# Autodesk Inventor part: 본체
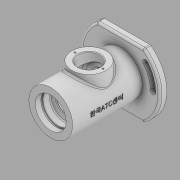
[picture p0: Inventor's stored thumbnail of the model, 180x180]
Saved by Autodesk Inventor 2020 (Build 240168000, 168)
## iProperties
Created: 2022-05
Part Number: 본체
Material: 일반
Document SubType Name: Modeling
Designer: Student
Mass: 254.633 g
Surface Area: 622.213 cm^2
Volume: 254.633 cm^3
Density: 1 g/cm^3
Appearance: 기본값
Author: Student
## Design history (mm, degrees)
sketch "스케치1"
  geometry: L1 (47, 92.583)-(47, -88.297); L2 (69.5, 10.285)-(69.5, 2.285); L3 (69.5, 2.285)-(71, 2.285); L4 (71, 2.285)-(71, -0.715); L5 (71, -0.715)-(69.5, -0.715); L6 (69.5, -0.715)-(69.5, -11.715); L7 (69.5, -11.715)-(65.5, -11.715); L8 (64.5, -12.715)-(64.5, -13.965); L9 (64.5, -13.965)-(65.5, -13.965); L10 (65.5, -13.965)-(65.5, -15.715); L11 (65.5, -15.715)-(64.5, -15.715); L12 (64.5, -15.715)-(64.5, -25.715); L13 (65.5, -26.715)-(71, -26.715); L14 (74, -29.715)-(74, -61.715); L15 (71, -64.715)-(65.5, -64.715); L16 (64.5, -65.715)-(64.5, -75.115); L17 (63.9, -75.715)-(62, -75.715); L18 (62, -75.715)-(62, -77.715); L19 (59, -80.715)-(58, -80.715); L20 (58, -80.715)-(58, -82.715); L21 (58, -82.715)-(61.5, -82.715); L22 (62, -83.215)-(62, -89.715); L23 (62.577, -90.715)-(65.456, -90.715); L24 (67.897, -91.971)-(77, -104.715); L25 (69.5, 10.285)-(79, 10.285); L26 (79, 10.285)-(79, -91.715); L27 (79, -91.715)-(105, -91.715); L28 (105, -91.715)-(105, -101.715); L29 (105, -101.715)-(83, -101.715); L30 (83, -101.715)-(83, -104.715); L31 (83, -104.715)-(77, -104.715); L32 (65.5, -11.715)-(64.5, -12.715); L33 (64.5, -25.715)-(65.5, -26.715); L34 (65.5, -64.715)-(64.5, -65.715); L35 (62, -89.715)-(62.577, -90.715); A1 r 3 centre (71, -29.715) between (74, -29.715) and (71, -26.715); A2 r 3 centre (71, -61.715) between (71, -64.715) and (74, -61.715); A3 r 0.6 centre (63.9, -75.115) between (63.9, -75.715) and (64.5, -75.115); A4 r 3 centre (59, -77.715) between (59, -80.715) and (62, -77.715); A5 r 0.5 centre (61.5, -83.215) between (62, -83.215) and (61.5, -82.715); A6 r 3 centre (65.456, -93.715) between (67.897, -91.971) and (65.456, -90.715); 11 further points
  constraints: 70 end point, 24 point on line, 23 perpendicular, 12 point on circle, 12 tangent, 6 centre point, 2 horizontal, 2 vertical, 1 equal radius
  dimensions: "d0" = 47 distance from line of point (0, 0) L1; "d3" = 22 diameter of L20 L1; "d4" = 48 diameter of L4 L1; "d6" = 45 diameter of L6 L1; "d7" = 45 diameter of L2 L1; "d8" = 35 diameter of L8 L1; "d10" = 54 diameter of L14 L1; "d11" = 30 diameter of L18 L1; "d12" = 40 diameter of point (67, -90.715) L1; "d13" = 30 diameter of L22 L1; "d14" = 60 diameter of L24.end L1; "d15" = 72 diameter of L30.end L1; "d16" = 64 diameter of L26 L1; "d17" = 8 distance of L2.start L2.end; "d18" = 3 distance of L3.end L4.end; "d20" = 37 diameter of L10 L1; "d21" = 1.75 distance of L9.end L10.end; "d22" = 4 vertical distance of L10.end point (64.5, -11.715); "d23" = 11 distance of L11.end point (64.5, -26.715); "d24" = 38 distance of point (74, -26.715) point (74, -64.715); "d25" = 11 distance of point (64.5, -64.715) point (64.5, -75.715); "d26" = 5 distance of L17.end point (62, -80.715); "d27" = 14 vertical distance of L24.end point (67, -90.715); "d28" = 115 distance from line of L24.end L25; "d29" = 3 distance of L29.end L30.end; "d30" = 13 distance from line of L30.end L27; "d31" = 116 diameter of L28 L1; "d32" = 8 distance of point (62, -90.715) point (62, -82.715); "d54" = 101.71474 distance from line of point (0, 0) L29; "d55" = 194.29758 distance from line of L1.start L29; "d56" = 13.41793 distance from line of L1.end L29; "d125" = 1 distance of L7.end point (64.5, -11.715); "d126" = 1 distance of L8.start point (64.5, -11.715) (= d125); "d127" = 1 distance of L12.end point (64.5, -26.715); "d128" = 1 distance of L13.start point (64.5, -26.715) (= d127); "d129" = 3 radius of A1; "d130" = 1 distance of L15.end point (64.5, -64.715); "d131" = 1 distance of L16.start point (64.5, -64.715) (= d130); "d132" = 0.6 radius of A3; "d133" = 3 radius of A4; "d134" = 0.5 radius of A5; "d135" = 1 distance of L22.end point (62, -90.715); "d136" = 30 deg angle of L22 L35; "d137" = 3 radius of A6; "d167" = 23 vertical distance of L8.start L2.start
revolve "회전1" sketch "스케치1" stored, may be unused: angle "d57" = 90 deg
sketch "스케치2"
  geometry: L1 (-48.645, 85.087)-(48.645, 85.087); L2 (48.645, 85.087)-(48.645, 47); L3 (48.645, 47)-(-48.645, 47); L4 (-48.645, 47)-(-48.645, 85.087); C1 r 11 at (0, 0) reference; 2 further points
  constraints: 8 end point, 2 parallel, 1 horizontal, 1 midpoint, 1 perpendicular, 1 vertical alignment
  dimensions: "d59" = 47 distance from line of C1.centre L3; "d63" = 38.08713 distance of L1.end L2.end; "d64" = 97.29056 distance of L1.start L1.end
extrude "돌출1" cut sketch "스케치2" distance "d60" = 10; taper "d61" = 0 deg
node "작업 평면1"
sketch "스케치7"
  geometry: 1 further point
sketch "스케치8"
  geometry: C1 r 32 at (0, 0) reference; 1 further point
hole "구멍3" sketch "스케치8" at (0, 0) diameter "d94" = 43.376; stored, may be unused: countersink angle "d98" = 90 deg, drill point angle "d100" = 118 deg; dims "d95" = 8, "d96" = 4, "d97" = 2, "d99" = 22
node "작업 평면2"
sketch "스케치9"
  geometry: L1 (-32, 10.285)-(32, 10.285) reference; C1 r 25 at (0, -45.715); 1 further point
  constraints: 1 centre point, 1 vertical alignment
  dimensions: "d102" = 25 radius of C1; "d103" = 56 distance from line of C1.centre L1
extrude "돌출4" join sketch "스케치9" stored distance "d104" = 4.4; taper "d105" = 5 deg
sketch "스케치10"
  geometry: C1 r 25 at (0, 0) reference; 1 further point
hole "구멍4" sketch "스케치10" at (0, 0) diameter "d106" = 32; stored, may be unused: countersink angle "d110" = 90 deg, drill point angle "d112" = 118 deg; dims "d107" = 8, "d108" = 4, "d109" = 2, "d111" = 22
sketch "스케치11"
  geometry: C1 r 16 at (0, 0) reference; 2 further points
  constraints: 1 horizontal alignment
  dimensions: "d113" = 20.5 distance of C1.centre point (-20.5, 0)
hole "구멍5" sketch "스케치11" at (-20.5, 0) diameter "d114" = 2.459; stored, may be unused: countersink angle "d118" = 90 deg, drill point angle "d120" = 118 deg; dims "d115" = 6, "d116" = 4, "d117" = 2, "d119" = 8
fillet "모깎기1" dims "d124" = 3
node "작업 평면3"
sketch "스케치12"
  geometry: L1 (0, -101.715)-(94, -101.715) reference; L2 (15, 10.285)-(79, 10.285) reference; L3 (94, -101.715)-(94, -91.715) reference; 2 further points
  constraints: 1 other
  dimensions: "d139" = 62 distance from line of L1 point (47, -39.715); "d140" = 47 distance from line of point (47, -39.715) L3
feature "엠보싱1" sketch "스케치12" dims "d141" = 0.5, "d142" = 0
fillet "모깎기2" dims "d143" = 3
fillet "모깎기3" dims "d144" = 3
sketch "스케치13"
  geometry: L1 (33, -44)-(69.77, -13.146); L2 (33, -44)-(81, -44); L3 (33, -44)-(-3.77, -74.854); L4 (33, -44)-(-15, -44); C1 r 20.897 at (33, -44) reference; A1 r 48 centre (33, -44) between (81, -44) and (69.77, -13.146); A2 r 52 centre (33, -44) between (85, -44) and (72.834, -10.575); A3 r 44 centre (33, -44) between (77, -44) and (66.706, -15.717); A4 r 4 centre (81, -44) between (77, -44) and (85, -44); A5 r 4 centre (69.77, -13.146) between (72.834, -10.575) and (66.706, -15.717); A6 r 48 centre (33, -44) between (-15, -44) and (-3.77, -74.854); A7 r 52 centre (33, -44) between (-19, -44) and (-6.834, -77.425); A8 r 44 centre (33, -44) between (-11, -44) and (-0.706, -72.283); A9 r 4 centre (-15, -44) between (-11, -44) and (-19, -44); A10 r 4 centre (-3.77, -74.854) between (-6.834, -77.425) and (-0.706, -72.283); 1 further point
  constraints: 20 point on circle, 10 centre point, 8 end point, 8 tangent, 2 coincident, 1 concentric, 1 horizontal
  dimensions: "d145" = 48 radius of A1; "d146" = 40 deg angle of L2 L1; "d147" = 4 radius of A5; "d148" = 48 radius of A6; "d149" = 40 deg angle of L4 L3; "d150" = 4 radius of A10 (derived); "d151" = 140 deg angle of L2 L3
extrude "돌출5" cut sketch "스케치13" distance "d152" = 4.4; taper "d153" = 0 deg
sketch "스케치14"
  geometry: A1 r 4 centre (-15, -44) between (-11, -44) and (-19, -44) reference; A2 r 52 centre (33, -44) between (-19, -44) and (-6.834, -77.425) reference; A3 r 4 centre (-3.77, -74.854) between (-6.834, -77.425) and (-0.706, -72.283) reference; A4 r 44 centre (33, -44) between (-11, -44) and (-0.706, -72.283) reference; A5 r 52 centre (33, -44) between (85, -44) and (72.834, -10.575) reference; A6 r 4 centre (69.77, -13.146) between (72.834, -10.575) and (66.706, -15.717) reference; A7 r 44 centre (33, -44) between (77, -44) and (66.706, -15.717) reference; A8 r 4 centre (81, -44) between (77, -44) and (85, -44) reference; A9 r 48 centre (33, -44) between (-15, -44) and (-3.77, -74.854); A10 r 50.25 centre (33, -44) between (-17.25, -44) and (-5.494, -76.3); A11 r 45.75 centre (33, -44) between (-12.75, -44) and (-2.047, -73.408); A12 r 2.25 centre (-15, -44) between (-12.75, -44) and (-17.25, -44); A13 r 2.25 centre (-3.77, -74.854) between (-5.494, -76.3) and (-2.047, -73.408); A14 r 48 centre (33, -44) between (81, -44) and (69.77, -13.146); A15 r 50.25 centre (33, -44) between (83.25, -44) and (71.494, -11.7); A16 r 45.75 centre (33, -44) between (78.75, -44) and (68.047, -14.592); A17 r 2.25 centre (81, -44) between (78.75, -44) and (83.25, -44); A18 r 2.25 centre (69.77, -13.146) between (71.494, -11.7) and (68.047, -14.592); 1 further point
  constraints: 20 point on circle, 10 centre point, 8 tangent, 2 coincident, 1 concentric
  dimensions: "d154" = 2.25 radius of A12
extrude "돌출6" cut sketch "스케치14" extent not by distance; stored distance "d155" = 0; taper "d156" = 0 deg
sketch "스케치15"
  geometry: A1 r 2.25 centre (-3.77, -16.146) between (-2.047, -17.592) and (-5.494, -14.7) reference; A2 r 2.25 centre (69.77, -77.854) between (68.047, -76.408) and (71.494, -79.3) reference; 1 further point
hole "구멍6" sketch "스케치15" at (-3.77, -16.146), (69.77, -77.854) diameter "d157" = 8; stored, may be unused: countersink angle "d161" = 90 deg, drill point angle "d163" = 118 deg; dims "d158" = 8, "d159" = 4, "d160" = 2, "d162" = 11
chamfer "모따기1" distance "d164" = 1; stored, may be unused: second distance "d165" = 2, angle "d166" = 45 deg
node "솔리드1"
mirror "미러1"
pattern_circular "원형 패턴1" dims angle "d122" = 360 deg
node "투영된 루프3"
node "투영된 루프4"
node "투영된 루프5"
feature "A9D066F2-1C7D-4E18-AEED-F7BC21143FA4" dims "d94" = 43.376, "d95" = 8, "d96" = 4, "d97" = 2, "d98" = 90 deg, "d99" = 22, "d100" = 118 deg
other parameters: "d62" = -47, "d101" = 85, "d138" = 33
